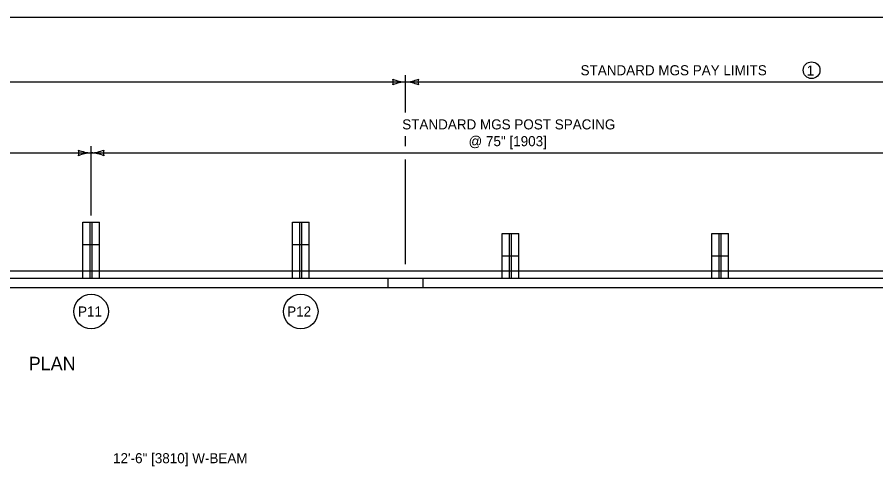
# Model space of a CAD drawing. Extents: x 49991 to 50160, y 49948 to 50051.
# Drawn here: x 50005.88 to 50011, y 49996.31 to 49999 of the extents above; entities that cross this region are included whole.
import ezdxf

# ---------------------------------------------------------------- set-up
doc = ezdxf.new("R2010")
doc.units = 0
for name, color, linetype in [('Level 1', 7, 'Continuous'), ('Level 2', 7, 'Continuous'), ('Level 3', 7, 'Continuous'), ('Level 4', 7, 'Continuous')]:
    doc.layers.add(name, color=color, linetype=linetype)

msp = doc.modelspace()

# ---------------------------------------------------------------- linework, layer by layer
at = {"layer": 'Level 1'}
for p, q in [((50006.2716, 49997.643), (50006.2716, 49997.7763)), ((50006.2716, 49997.7763), (50006.3716, 49997.7763)), ((50006.3716, 49997.643), (50006.3716, 49997.7763)), ((50007.5216, 49997.6429), (50007.5216, 49997.7762)), ((50007.5216, 49997.7762), (50007.6216, 49997.7762)), ((50007.6216, 49997.6429), (50007.6216, 49997.7762)), ((50008.7716, 49997.5762), (50008.7716, 49997.7095)), ((50008.7716, 49997.7095), (50008.8716, 49997.7095)), ((50008.8716, 49997.5762), (50008.8716, 49997.7095)), ((50010.0216, 49997.5761), (50010.0216, 49997.7095)), ((50010.0216, 49997.7095), (50010.1216, 49997.7095)), ((50010.1216, 49997.5761), (50010.1216, 49997.7095)), ((50006.2716, 49997.443), (50006.2716, 49997.643)), ((50006.2716, 49997.643), (50006.3716, 49997.643)), ((50006.2716, 49997.643), (50006.3716, 49997.643)), ((50006.3716, 49997.443), (50006.3716, 49997.643)), ((50007.5216, 49997.4429), (50007.5216, 49997.6429)), ((50007.5216, 49997.6429), (50007.6216, 49997.6429)), ((50007.5216, 49997.6429), (50007.6216, 49997.6429)), ((50007.6216, 49997.4429), (50007.6216, 49997.6429)), ((50008.7716, 49997.4429), (50008.7716, 49997.5762)), ((50008.7716, 49997.5762), (50008.8716, 49997.5762)), ((50008.7716, 49997.5762), (50008.8716, 49997.5762)), ((50008.8716, 49997.4429), (50008.8716, 49997.5762)), ((50010.0216, 49997.4428), (50010.0216, 49997.5761)), ((50010.0216, 49997.5761), (50010.1216, 49997.5761)), ((50010.0216, 49997.5761), (50010.1216, 49997.5761)), ((50010.1216, 49997.4428), (50010.1216, 49997.5761)), ((50005.7466, 49997.4869), (50006.2716, 49997.4869)), ((50006.3716, 49997.4868), (50007.5216, 49997.4868)), ((50007.6216, 49997.4868), (50008.7716, 49997.4868)), ((50008.8716, 49997.4868), (50010.0216, 49997.4868)), ((50010.1216, 49997.4868), (50011.2716, 49997.4867)), ((49999.8072, 49997.4432), (50011.6716, 49997.4427)), ((50006.2716, 49997.443), (50006.3716, 49997.443)), ((50007.5216, 49997.4429), (50007.6216, 49997.4429)), ((50008.0917, 49997.3868), (50008.0917, 49997.4429)), ((50008.7716, 49997.4429), (50008.8716, 49997.4429)), ((50010.0216, 49997.4428), (50010.1216, 49997.4428)), ((49999.8072, 49997.387), (50011.6716, 49997.3865))]:
    msp.add_line(p, q, dxfattribs=at)
msp.add_lwpolyline([(49999.3835, 49998.9992), (50016.7501, 49998.9992), (50016.7501, 49987.7988), (49999.3835, 49987.7988)], close=True, dxfattribs=at)
at = {"layer": 'Level 2'}
for centre, radius in [((50010.6171, 49998.6827), 0.05), ((50006.3216, 49997.2441), 0.1026), ((50007.5716, 49997.2441), 0.1026)]:
    msp.add_circle(centre, radius, dxfattribs=at)
at = {"layer": 'Level 3'}
for p, q in [((50008.1966, 49998.4299), (50008.1966, 49998.6527)), ((50000.679, 49998.6127), (50008.1966, 49998.6127)), ((50008.1966, 49998.6127), (50011.5324, 49998.6127)), ((50008.1966, 49998.2299), (50008.1966, 49998.2899)), ((50006.3216, 49997.8163), (50006.3216, 49998.2299)), ((50003.8216, 49998.1899), (50006.3216, 49998.1899)), ((50006.3216, 49998.1899), (50011.5324, 49998.1899)), ((50008.1966, 49997.5268), (50008.1966, 49998.1499))]:
    msp.add_line(p, q, dxfattribs=at)
for centre, radius, start, end in [((50008.2058, 49998.8348), 0.2223, 247.456, 267.6395), ((50008.0684, 49998.6127), 0.0548, 342.1388, 17.8612), ((50008.2081, 49998.38), 0.233, 92.8273, 112.0772), ((50008.1852, 49998.8454), 0.233, 272.8273, 292.0772), ((50008.1875, 49998.3905), 0.2223, 67.456, 87.6395), ((50008.3249, 49998.6127), 0.0548, 162.1388, 197.8612), ((50006.3308, 49998.412), 0.2223, 247.456, 267.6395), ((50006.1934, 49998.1899), 0.0548, 342.1388, 17.8612), ((50006.3331, 49997.9572), 0.233, 92.8273, 112.0772), ((50006.3102, 49998.4226), 0.233, 272.8273, 292.0772), ((50006.3125, 49997.9678), 0.2223, 67.456, 87.6395), ((50006.4499, 49998.1899), 0.0548, 162.1388, 197.8612)]:
    msp.add_arc(centre, radius, start, end, dxfattribs=at)
at = {"layer": 'Level 4'}
for p, q in [((50006.3154, 49997.643), (50006.3154, 49997.7763)), ((50006.3279, 49997.643), (50006.3279, 49997.7763)), ((50007.5654, 49997.6429), (50007.5654, 49997.7762)), ((50007.5779, 49997.6429), (50007.5779, 49997.7762)), ((50008.8154, 49997.5762), (50008.8154, 49997.7095)), ((50008.8279, 49997.5762), (50008.8279, 49997.7095)), ((50010.0654, 49997.5761), (50010.0654, 49997.7095)), ((50010.0779, 49997.5761), (50010.0779, 49997.7095)), ((50006.3154, 49997.443), (50006.3154, 49997.643)), ((50006.3279, 49997.443), (50006.3279, 49997.643)), ((50007.5654, 49997.4429), (50007.5654, 49997.6429)), ((50007.5779, 49997.4429), (50007.5779, 49997.6429)), ((50008.8154, 49997.4429), (50008.8154, 49997.5762)), ((50008.8279, 49997.4429), (50008.8279, 49997.5762)), ((50010.0654, 49997.4428), (50010.0654, 49997.5761)), ((50010.0779, 49997.4428), (50010.0779, 49997.5761)), ((50006.2716, 49997.4869), (50006.3716, 49997.4868)), ((50007.5216, 49997.4868), (50007.6216, 49997.4868)), ((50008.7716, 49997.4868), (50008.8716, 49997.4868)), ((50010.0216, 49997.4867), (50010.1216, 49997.4867)), ((50008.3016, 49997.3868), (50008.3016, 49997.4429))]:
    msp.add_line(p, q, dxfattribs=at)

# ---------------------------------------------------------------- texts
at = {"layer": 'Level 2'}
for s, height, p in [('STANDARD MGS PAY LIMITS', 0.06, (50009.2397, 49998.6527)), ('1', 0.06, (50010.5879, 49998.651)), ('STANDARD MGS POST SPACING', 0.06, (50008.1763, 49998.3299)), ('@ 75" [1903]', 0.06, (50008.5718, 49998.2299)), ('P11', 0.06, (50006.2434, 49997.2143)), ('P12', 0.06, (50007.4904, 49997.2143)), ('PLAN', 0.08, (50005.9494, 49996.894)), ('12\'-6" [3810] W-BEAM', 0.06, (50006.4522, 49996.3394))]:
    msp.add_text(s, height=height, dxfattribs=at).set_placement(p)

doc.saveas('drawing.dxf')
